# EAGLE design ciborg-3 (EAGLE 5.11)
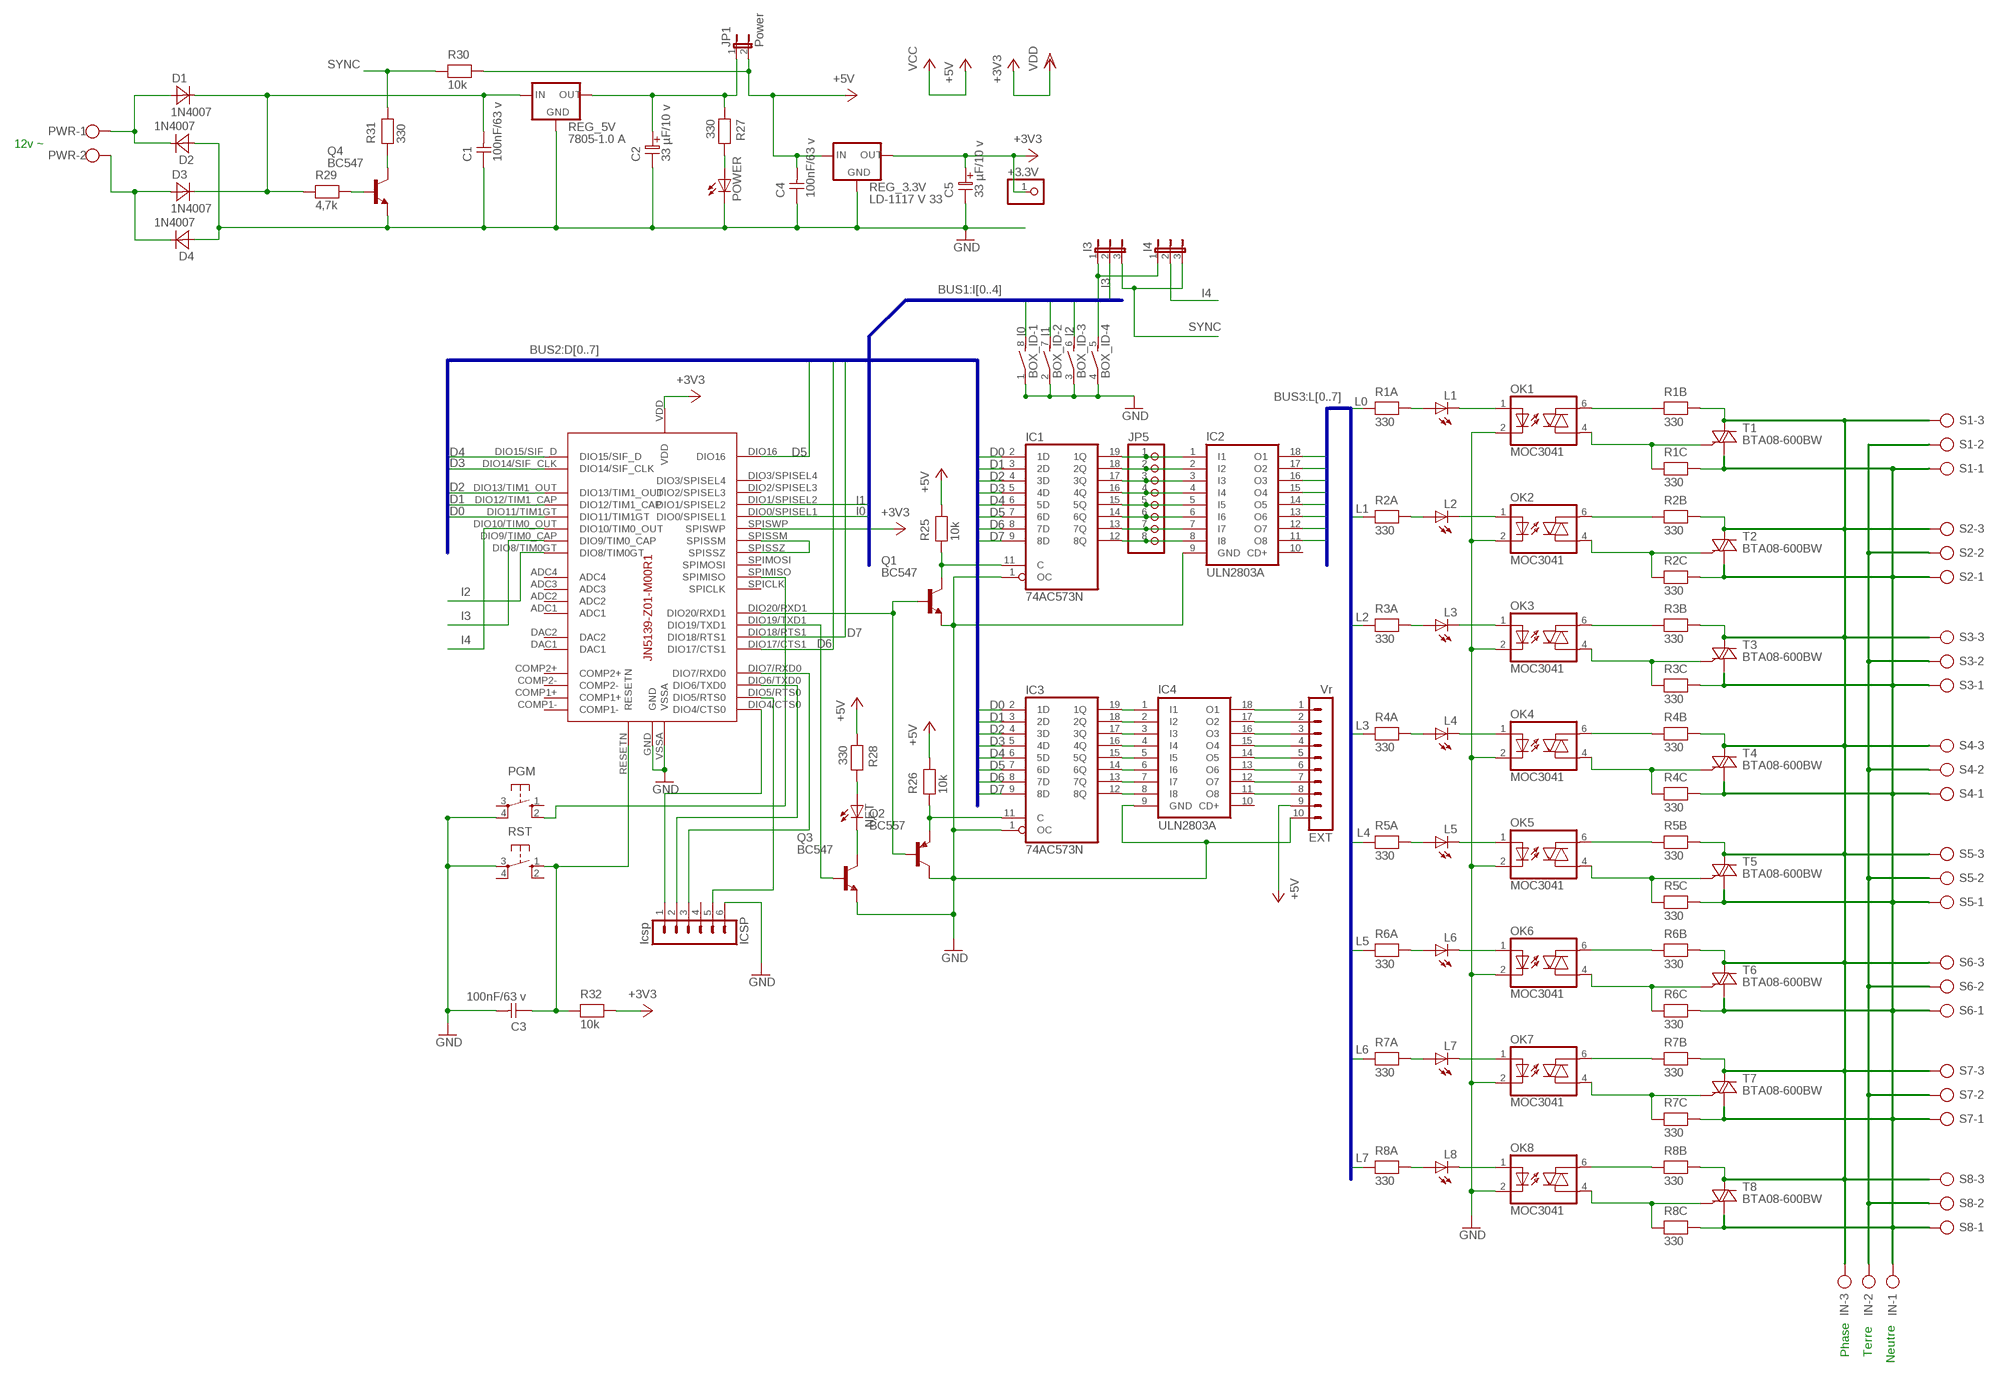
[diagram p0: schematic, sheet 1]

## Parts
+3.3V  PINHD-1X1  [1X01]
BOX_ID  DIP04S  [DIP04S]
C1  100nF/63 v  CAPNP-5  [C-5]
C2  33 µF/10 v  ELC-2,5L  [ES-2,5L]
C3  100nF/63 v  CAPNP-5  [C-5]
C4  100nF/63 v  CAPNP-5  [C-5]
C5  33 µF/10 v  ELC-2,5L  [ES-2,5L]
D1  1N4007  DIODE-10  [D-10]
D2  1N4007  DIODE-10  [D-10]
D3  1N4007  DIODE-10  [D-10]
D4  1N4007  DIODE-10  [D-10]
EXT  Vr  MA10-1  [MA10-1]
I3  JP2E  [JP2]
I4  JP2E  [JP2]
IC1  74AC573N  [DIL20]
IC2  ULN2803A  [DIL18]
IC3  74AC573N  [DIL20]
IC4  ULN2803A  [DIL18]
ICSP  Icsp  MA06-1  [MA06-1]
IN  AK500/3  [AK500/3]
JP1  Power  JP1E  [JP1]
JP5  PINHD-1X8  [1X08]
L1  LED3MM  [LED3MM]
L2  LED3MM  [LED3MM]
L3  LED3MM  [LED3MM]
L4  LED3MM  [LED3MM]
L5  LED3MM  [LED3MM]
L6  LED3MM  [LED3MM]
L7  LED3MM  [LED3MM]
L8  LED3MM  [LED3MM]
NET  LED3MM  [LED3MM]
OK1  MOC3041  IL420  [DIL06]
OK2  MOC3041  IL420  [DIL06]
OK3  MOC3041  IL420  [DIL06]
OK4  MOC3041  IL420  [DIL06]
OK5  MOC3041  IL420  [DIL06]
OK6  MOC3041  IL420  [DIL06]
OK7  MOC3041  IL420  [DIL06]
OK8  MOC3041  IL420  [DIL06]
PGM  10-XX  [B3F-10XX]
POWER  LED3MM  [LED3MM]
PWR  AK550/2  [AK550/2]
Q1  BC547  [TO92]
Q2  BC557  [TO92]
Q3  BC547  [TO92]
Q4  BC547  [TO92]
R1A  330  RESEU-7,5  [R-7,5]
R1B  330  RESEU-7,5  [R-7,5]
R1C  330  RESEU-7,5  [R-7,5]
R2A  330  RESEU-7,5  [R-7,5]
R2B  330  RESEU-7,5  [R-7,5]
R2C  330  RESEU-7,5  [R-7,5]
R3A  330  RESEU-7,5  [R-7,5]
R3B  330  RESEU-7,5  [R-7,5]
R3C  330  RESEU-7,5  [R-7,5]
R4A  330  RESEU-7,5  [R-7,5]
R4B  330  RESEU-7,5  [R-7,5]
R4C  330  RESEU-7,5  [R-7,5]
R5A  330  RESEU-7,5  [R-7,5]
R5B  330  RESEU-7,5  [R-7,5]
R5C  330  RESEU-7,5  [R-7,5]
R6A  330  RESEU-7,5  [R-7,5]
R6B  330  RESEU-7,5  [R-7,5]
R6C  330  RESEU-7,5  [R-7,5]
R7A  330  RESEU-7,5  [R-7,5]
R7B  330  RESEU-7,5  [R-7,5]
R7C  330  RESEU-7,5  [R-7,5]
R8A  330  RESEU-7,5  [R-7,5]
R8B  330  RESEU-7,5  [R-7,5]
R8C  330  RESEU-7,5  [R-7,5]
R25  10k  RESEU-7,5  [R-7,5]
R26  10k  RESEU-7,5  [R-7,5]
R27  330  RESEU-7,5  [R-7,5]
R28  330  RESEU-7,5  [R-7,5]
R29  4,7k  RESEU-7,5  [R-7,5]
R30  10k  RESEU-7,5  [R-7,5]
R31  330  RESEU-7,5  [R-7,5]
R32  10k  RESEU-7,5  [R-7,5]
REG_3.3V  LD-1117 V 33  78XXS  [78XXS]
REG_5V  7805-1.0 A  78XXS  [78XXS]
RST  10-XX  [B3F-10XX]
S1  AK500/3  [AK500/3]
S2  AK500/3  [AK500/3]
S3  AK500/3  [AK500/3]
S4  AK500/3  [AK500/3]
S5  AK500/3  [AK500/3]
S6  AK500/3  [AK500/3]
S7  AK500/3  [AK500/3]
S8  AK500/3  [AK500/3]
T1  BTA08-600BW  TIC225S  [TO220DS]
T2  BTA08-600BW  TIC225S  [TO220DS]
T3  BTA08-600BW  TIC225S  [TO220DS]
T4  BTA08-600BW  TIC225S  [TO220DS]
T5  BTA08-600BW  TIC225S  [TO220DS]
T6  BTA08-600BW  TIC225S  [TO220DS]
T7  BTA08-600BW  TIC225S  [TO220DS]
T8  BTA08-600BW  TIC225S  [TO220DS]
U1  JN5139-Z01-M00R1  [JENNIC5139MODULE]

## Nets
D0: IC1.2(1D) IC3.2(1D) U1.DIO11/TIM1GT
D1: IC1.3(2D) IC3.3(2D) U1.DIO12/TIM1_CAP
D2: IC1.4(3D) IC3.4(3D) U1.DIO13/TIM1_OUT
D3: IC1.5(4D) IC3.5(4D) U1.DIO14/SIF_CLK
D4: IC1.6(5D) IC3.6(5D) U1.DIO15/SIF_D
D5: IC1.7(6D) IC3.7(6D) U1.DIO16
D6: IC1.8(7D) IC3.8(7D) U1.DIO17/CTS1
D7: IC1.9(8D) IC3.9(8D) U1.DIO18/RTS1
GND: BOX_ID.1 BOX_ID.2 BOX_ID.3 BOX_ID.4 C1.1 C2.2 C3.2 C4.1 C5.2 D2.1(A) D4.1(A) EXT.10 IC1.1(OC) IC2.9(GND) IC3.1(OC) IC4.9(GND) ICSP.6 OK1.2(C) OK2.2(C) OK3.2(C) OK4.2(C) OK5.2(C) OK6.2(C) OK7.2(C) OK8.2(C) PGM.4(P1) POWER.K(C) Q1.1(E) Q2.3(C) Q3.1(E) Q4.1(E) REG_3.3V.GND REG_5V.GND RST.3(P) U1.GND U1.VSSA
I0: BOX_ID.8 U1.DIO0/SPISEL1
I1: BOX_ID.7 U1.DIO1/SPISEL2
I2: BOX_ID.6 U1.DIO8/TIM0GT
I3: I3.2 U1.DIO9/TIM0_CAP
I4: I4.2 U1.DIO10/TIM0_OUT
L0: IC2.18(O1) R1A.1
L1: IC2.17(O2) R2A.1
L2: IC2.16(O3) R3A.1
L3: IC2.15(O4) R4A.1
L4: IC2.14(O5) R5A.1
L5: IC2.13(O6) R6A.1
L6: IC2.12(O7) R7A.1
L7: IC2.11(O8) R8A.1
N$1: L4.K(C) OK4.1(A)
N$2: C2.1 JP1.1 R27.1 REG_5V.OUT
N$3: IC1.19(1Q) IC2.1(I1) JP5.1
N$4: IC1.18(2Q) IC2.2(I2) JP5.2
N$5: EXT.1 IC4.18(O1)
N$6: OK2.4(A1) R2C.1 T2.G
N$7: C3.1 R32.1 RST.1(S) U1.RESETN
N$8: OK1.4(A1) R1C.1 T1.G
N$9: EXT.2 IC4.17(O2)
N$10: OK3.4(A1) R3C.1 T3.G
N$11: EXT.3 IC4.16(O3)
N$12: OK4.4(A1) R4C.1 T4.G
N$13: L1.K(C) OK1.1(A)
N$14: EXT.4 IC4.15(O4)
N$15: OK5.4(A1) R5C.1 T5.G
N$16: EXT.5 IC4.14(O5)
N$17: L2.K(C) OK2.1(A)
N$18: OK6.4(A1) R6C.1 T6.G
N$19: L3.K(C) OK3.1(A)
N$20: EXT.6 IC4.13(O6)
N$21: OK7.4(A1) R7C.1 T7.G
N$22: L5.K(C) OK5.1(A)
N$23: EXT.7 IC4.12(O7)
N$24: OK8.4(A1) R8C.1 T8.G
N$25: OK1.6(A2) R1B.1
N$26: OK2.6(A2) R2B.1
N$27: L6.K(C) OK6.1(A)
N$28: EXT.8 IC4.11(O8)
N$29: C1.2 D1.2(K) D3.2(K) R29.1 REG_5V.IN
N$30: OK3.6(A2) R3B.1
N$31: OK4.6(A2) R4B.1
N$32: L7.K(C) OK7.1(A)
N$33: OK5.6(A2) R5B.1
N$34: OK6.6(A2) R6B.1
N$35: OK7.6(A2) R7B.1
N$36: OK8.6(A2) R8B.1
N$37: L8.K(C) OK8.1(A)
N$38: NET.K(C) Q3.3(C)
N$39: IC1.17(3Q) IC2.3(I3) JP5.3
N$40: IC1.16(4Q) IC2.4(I4) JP5.4
N$41: IC1.15(5Q) IC2.5(I5) JP5.5
N$42: IC1.14(6Q) IC2.6(I6) JP5.6
N$43: IC1.13(7Q) IC2.7(I7) JP5.7
N$44: IC1.12(8Q) IC2.8(I8) JP5.8
N$45: IC3.19(1Q) IC4.1(I1)
N$46: IC3.18(2Q) IC4.2(I2)
N$47: IC3.17(3Q) IC4.3(I3)
N$48: IC3.16(4Q) IC4.4(I4)
N$49: IC3.15(5Q) IC4.5(I5)
N$50: IC3.14(6Q) IC4.6(I6)
N$51: IC3.13(7Q) IC4.7(I7)
N$52: IC3.12(8Q) IC4.8(I8)
N$53: L2.A R2A.2
N$54: L3.A R3A.2
N$55: L4.A R4A.2
N$56: L5.A R5A.2
N$57: L6.A R6A.2
N$58: L7.A R7A.2
N$59: L8.A R8A.2
N$60: L1.A R1A.2
N$61: IC1.11(C) Q1.3(C) R25.1
N$62: NET.A R28.2
N$63: IC3.11(C) Q2.1(E) R26.1
N$64: Q1.2(B) Q2.2(B) U1.DIO20/RXD1
N$65: POWER.A R27.2
N$66: BOX_ID.5 I3.1 I4.1
N$67: ICSP.2 U1.DIO6/TXD0
N$68: D1.1(A) D2.2(K) PWR.1
N$69: D3.1(A) D4.2(K) PWR.2
N$70: PGM.2(S1) U1.SPIMISO
N$71: Q4.2(B) R29.2
N$72: Q4.3(C) R31.1
N$73: ICSP.1 U1.DIO4/CTS0
N$74: ICSP.5 U1.DIO5/RTS0
N$75: Q3.2(B) U1.DIO19/TXD1
N$76: U1.SPISSM U1.SPISSZ
N$77: ICSP.3 U1.DIO7/RXD0
NEUTRE [AC_VOLTAGE]: IN.1 R1C.2 R2C.2 R3C.2 R4C.2 R5C.2 R6C.2 R7C.2 R8C.2 S1.1 S2.1 S3.1 S4.1 S5.1 S6.1 S7.1 S8.1 T1.A1 T2.A1 T3.A1 T4.A1 T5.A1 T6.A1 T7.A1 T8.A1
PHASE [AC_VOLTAGE]: IN.3 R1B.2 R2B.2 R3B.2 R4B.2 R5B.2 R6B.2 R7B.2 R8B.2 S1.3 S2.3 S3.3 S4.3 S5.3 S6.3 S7.3 S8.3 T1.A2 T2.A2 T3.A2 T4.A2 T5.A2 T6.A2 T7.A2 T8.A2
SYNC: I3.3 I4.3 R30.1 R31.2
TERRE: IN.2 S1.2 S2.2 S3.2 S4.2 S5.2 S6.2 S7.2 S8.2
VCC: C4.2 EXT.9 JP1.2 R25.2 R26.2 R28.1 R30.2 REG_3.3V.IN ; supply symbol labelled +5V
VDD: +3.3V.1 C5.1 R32.2 REG_3.3V.OUT U1.SPISWP U1.VDD ; supply symbol labelled +3V3
Unconnected: IC2.10(CD+) IC4.10(CD+) ICSP.4 PGM.1(S) PGM.3(P) RST.2(S1) RST.4(P1) U1.ADC1 U1.ADC2 U1.ADC3 U1.ADC4 U1.COMP1+ U1.COMP1- U1.COMP2+ U1.COMP2- U1.DAC1 U1.DAC2 U1.DIO2/SPISEL3 U1.DIO3/SPISEL4 U1.SPICLK U1.SPIMOSI

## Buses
BUS3:L[0..7]
BUS2:D[0..7]
BUS1:I[0..4]

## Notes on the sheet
- 12v ~
- Phase | Neutre
- Terre

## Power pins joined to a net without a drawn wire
GND: IC1.10(GND) IC3.10(GND)
VCC: IC1.20(VCC) IC3.20(VCC)

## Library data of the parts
+3.3V = pinhead:PINHD-1X1: PIN HEADER
BOX_ID = switch-dil:DIP04S: DIL/CODE SWITCH; OC_FARNELL: unknown; OC_NEWARK: unknown
C1 C3 C4 = discrete:CAPNP-5
C2 C5 = discrete:ELC-2,5L
D1-D4 = discrete:DIODE-10
EXT = con-lstb:MA10-1: PIN HEADER; OC_FARNELL: unknown; OC_NEWARK: unknown
I3 I4 = jumper:JP2E: JUMPER
IC1 IC3 = 74xx-eu:74*573: 8-bit D latch BUS DRIVER
IC2 IC4 = uln-udn:ULN2803A: DRIVER ARRAY
ICSP = con-lstb:MA06-1: PIN HEADER; OC_FARNELL: unknown; OC_NEWARK: unknown
IN S1-S8 = con-ptr500:AK500/3: CONNECTOR
JP1 = jumper:JP1E: JUMPER
JP5 = pinhead:PINHD-1X8: PIN HEADER
L1-L8 NET POWER = led:LED: LED
OK1-OK8 = optocoupler:IL420: SIEMENS OPTO COUPLER
PGM RST = switch-omron:10-XX: OMRON SWITCH; MPN: B3F-1000; OC_FARNELL: 176432; OC_NEWARK: 36M3542
PWR = con-ptr500+:AK550/2: CONNECTOR
Q1 Q3 Q4 = transistor:BC547: NPN TRANSISTOR
Q2 = transistor-pnp:BC557: PNP Transistor
R1A R1B R1C R2A R2B R2C R3A R3B R3C R4A R4B R4C R5A R5B R5C R6A R6B R6C R7A R7B R7C R8A R8B R8C R25-R32 = discrete:RESEU-7,5
REG_3.3V REG_5V = v-reg:78XXS: VOLTAGE REGULATOR
T1-T8 = triac:TIC225S: TRIAC
U1 = jennic:JN5139-Z01-M00R1: Jennic 5139 Zigbee Module

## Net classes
0 default: width 0.254 mm, clearance 0.254 mm
1 AC_VOLTAGE: width 1.5 mm, clearance 0.254 mm
2 AC_TERRE: width 1.422 mm, clearance 0.254 mm

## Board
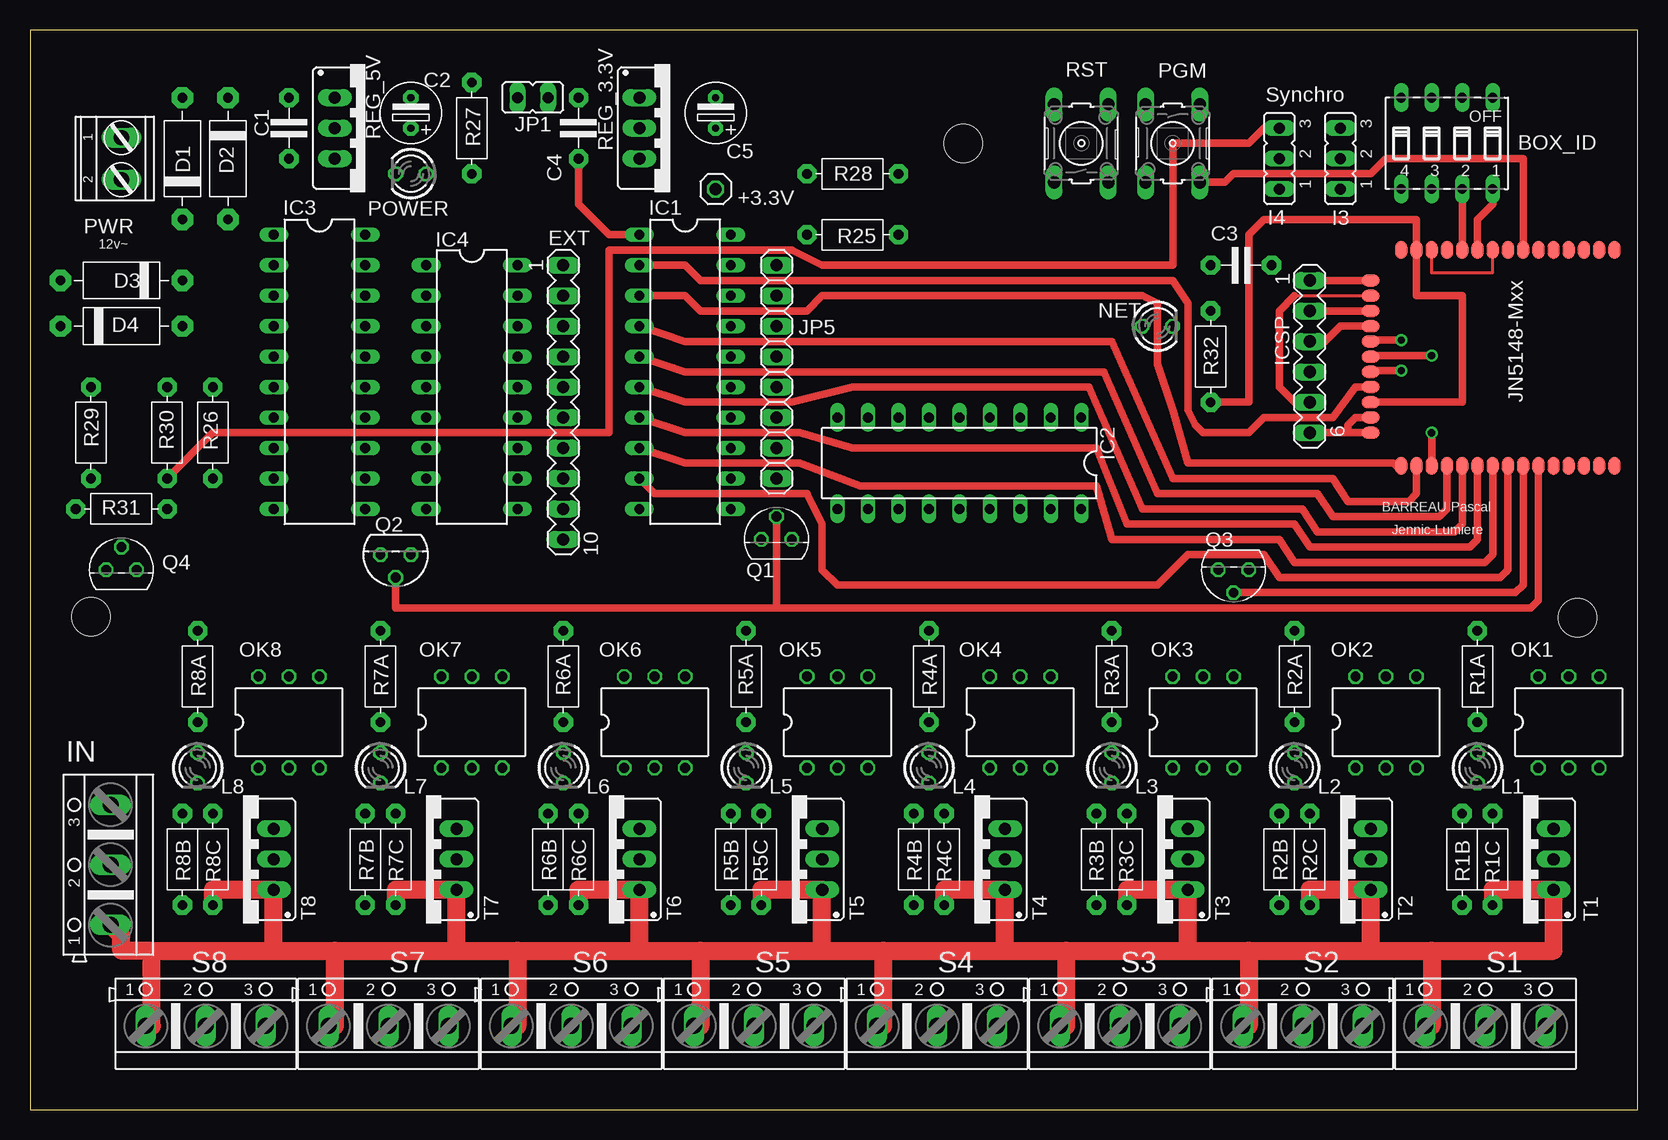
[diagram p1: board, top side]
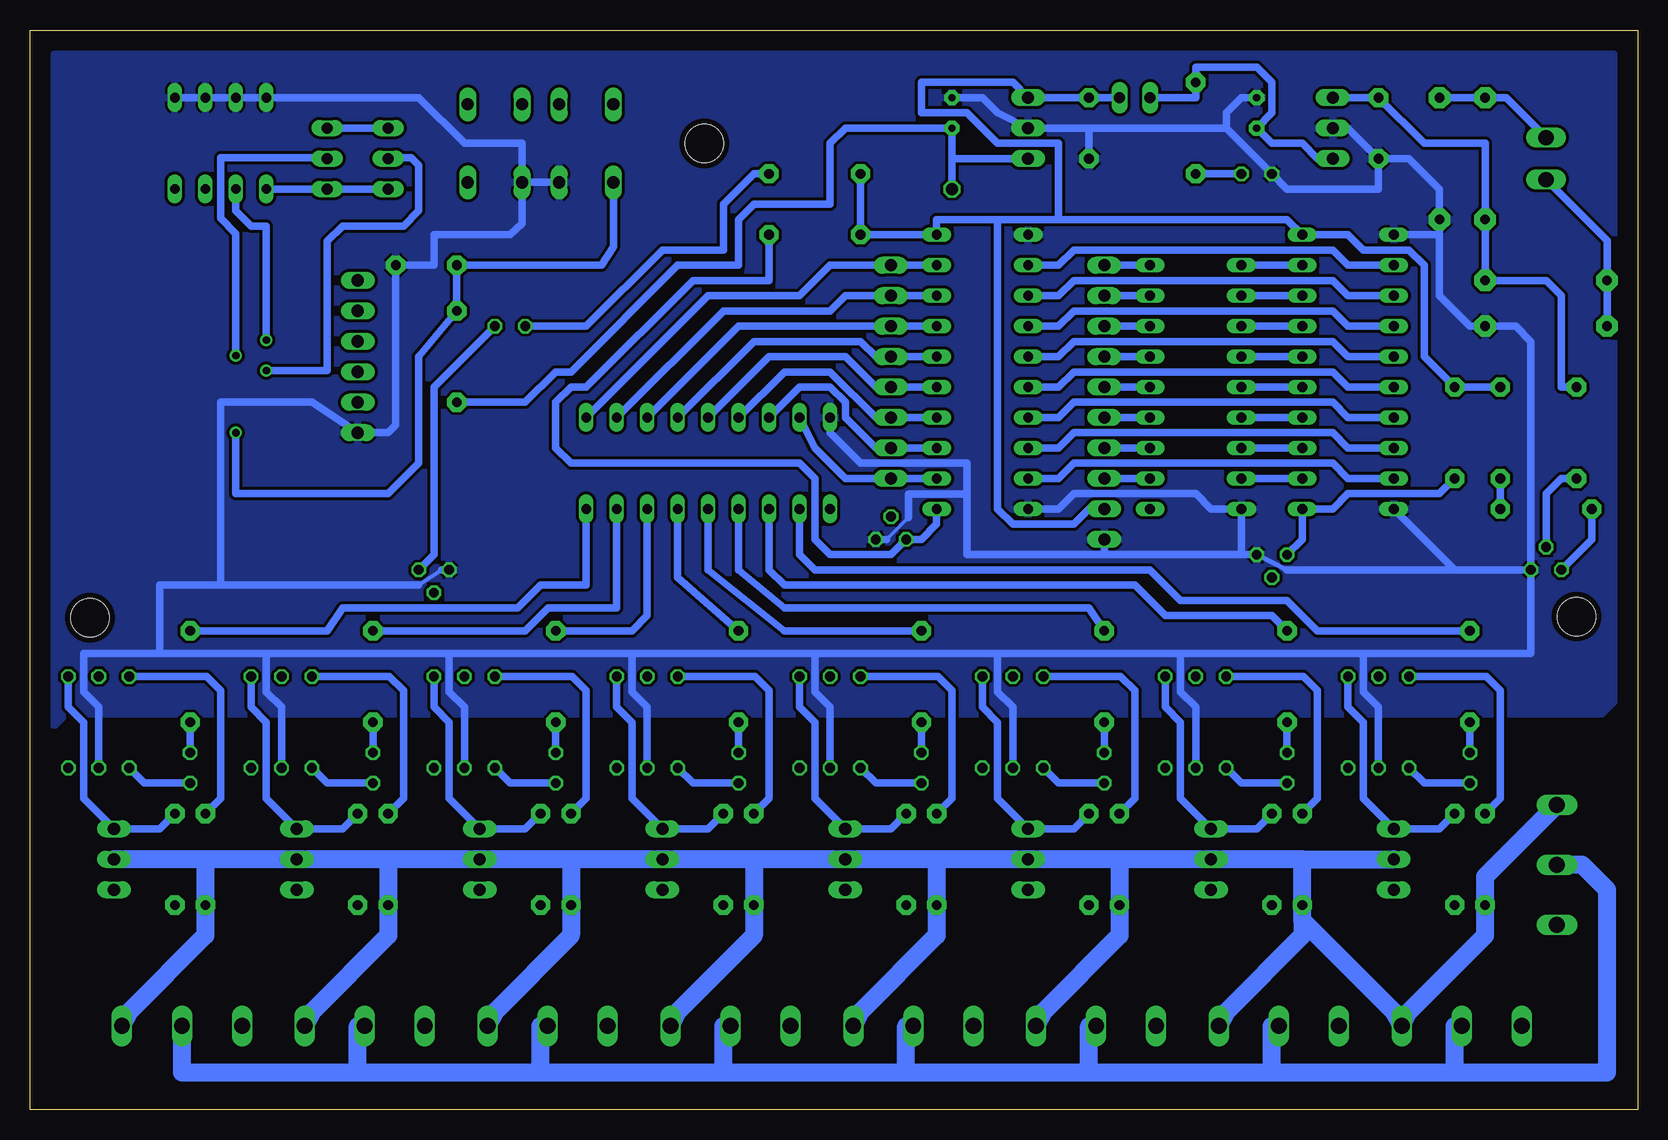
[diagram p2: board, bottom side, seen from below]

Size 134 x 90 mm. Coordinates in mm from the lower left corner, seen from the top.
Outline: 0,0 134,0 134,90 0,90 0,0
Copper layers (1*16): Top 0.018mm / dielectric 1.55mm / Bottom 0.018mm
Design rules "eC-PCB_proto-2-layer": minimum track width 0.15mm, minimum drill 0.25mm, track to track 0.15mm, track to pad 0.15mm, pad to pad 0.15mm, via to via 0.15mm, smd to smd 0.15mm, copper to edge 0.45mm, drill to drill 0.3mm, minimum pad ring 0.2mm, minimum via ring 0.2mm, stop-mask expansion 0.1mm, vias tented up to drill 0mil, thermal gap 0.2mm
Holes 3.2 mm at 129,41 77.8,80.55 5.08,41.1

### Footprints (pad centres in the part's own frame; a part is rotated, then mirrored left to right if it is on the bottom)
1X01 = drill 1.016 octagon: 1 0,0
DIP04S = drill 0.813 long: 1 -3.81,-3.81; 2 -1.27,-3.81; 3 1.27,-3.81; 4 3.81,-3.81; 5 3.81,3.81; 6 1.27,3.81; 7 -1.27,3.81; 8 -3.81,3.81
C-5 = drill 0.813 pad 1.6 octagon: 1 -2.54,0; 2 2.54,0
ES-2,5L = drill 0.61 pad 1.27 octagon: 1 0,0; 2 2.54,0
D-10 = drill 0.813 pad 1.778 octagon: 1 -5.08,0; 2 5.08,0
MA10-1 = drill 1.016 long: 1 -11.43,0; 2 -8.89,0; 3 -6.35,0; 4 -3.81,0; 5 -1.27,0; 6 1.27,0; 7 3.81,0; 8 6.35,0; 9 8.89,0; 10 11.43,0
JP2 = drill 0.914 long: 1 -2.54,0; 2 0,0; 3 2.54,0
DIL20 = drill 0.813 long: 1 -11.43,-3.81; 2 -8.89,-3.81; 3 -6.35,-3.81; 4 -3.81,-3.81; 5 -1.27,-3.81; 6 1.27,-3.81; 7 3.81,-3.81; 8 6.35,-3.81; 9 8.89,-3.81; 10 11.43,-3.81; 11 11.43,3.81; 12 8.89,3.81; 13 6.35,3.81; 14 3.81,3.81; 15 1.27,3.81; 16 -1.27,3.81; 17 -3.81,3.81; 18 -6.35,3.81; 19 -8.89,3.81; 20 -11.43,3.81
DIL18 = drill 0.813 long: 1 -10.16,-3.81; 2 -7.62,-3.81; 3 -5.08,-3.81; 4 -2.54,-3.81; 5 0,-3.81; 6 2.54,-3.81; 7 5.08,-3.81; 8 7.62,-3.81; 9 10.16,-3.81; 10 10.16,3.81; 11 7.62,3.81; 12 5.08,3.81; 13 2.54,3.81; 14 0,3.81; 15 -2.54,3.81; 16 -5.08,3.81; 17 -7.62,3.81; 18 -10.16,3.81
MA06-1 = drill 1.016 long: 1 -6.35,0; 2 -3.81,0; 3 -1.27,0; 4 1.27,0; 5 3.81,0; 6 6.35,0
AK500/3 = drill 1.321 long: 1 -5.004,0; 2 0,0; 3 5.004,0
JP1 = drill 0.914 long: 1 0,-1.27; 2 0,1.27
1X08 = drill 1.016 long: 1 -8.89,0; 2 -6.35,0; 3 -3.81,0; 4 -1.27,0; 5 1.27,0; 6 3.81,0; 7 6.35,0; 8 8.89,0
LED3MM = drill 0.813 octagon: A -1.27,0; K 1.27,0
DIL06 = drill 0.813 octagon: 1 -2.54,-3.81; 2 0,-3.81; 3 2.54,-3.81; 4 2.54,3.81; 5 0,3.81; 6 -2.54,3.81
B3F-10XX = drill 1.016 long: 1 -3.251,2.261; 2 3.251,2.261; 3 -3.251,-2.261; 4 3.251,-2.261
AK550/2 = drill 1.27 long: 1 -1.75,0; 2 1.75,0
TO92 = drill 0.813 octagon: 1 1.27,0; 2 0,1.905; 3 -1.27,0
R-7,5 = drill 0.813 pad 1.6 octagon: 1 -3.81,0; 2 3.81,0
78XXS = drill 1.016 long: GND 0,-2.54; IN -2.54,-2.54; OUT 2.54,-2.54
TO220DS = drill 1.016 long: A1 -2.54,-2.54; A2 0,-2.54; G 2.54,-2.54
JENNIC5139MODULE = smd 1.5 x 1: ADC1 18,17.78; ADC2 18,19.05; ADC3 18,20.32; ADC4 0,20.32; COMP1+ 18,16.51; COMP1- 18,15.24; COMP2+ 0,16.51; COMP2- 0,15.24; DAC1 0,19.05; DAC2 0,17.78; DIO0/SPISEL1 0,8.89; DIO1/SPISEL2 0,7.62; DIO2/SPISEL3 0,6.35; DIO3/SPISEL4 0,2.54; DIO12/TIM1_CAP 18,2.54; DIO13/TIM1_OUT 18,3.81; DIO14/SIF_CLK 18,6.35; DIO15/SIF_D 18,7.62; DIO16 18,8.89; DIO17/CTS1 18,10.16; DIO18/RTS1 18,11.43; DIO19/TXD1 18,12.7; DIO20/RXD1 18,13.97; RESETN 18,5.08; SPICLK 0,13.97; SPIMISO 0,12.7; SPIMOSI 0,11.43; SPISSM 0,5.08; SPISSZ 0,10.16; SPISWP 0,3.81 | smd 1 x 1.5: DIO4/CTS0 2.54,0; DIO5/RTS0 3.81,0; DIO6/TXD0 5.08,0; DIO7/RXD0 6.35,0; DIO8/TIM0GT 7.62,0; DIO9/TIM0_CAP 8.89,0; DIO10/TIM0_OUT 10.16,0; DIO11/TIM1GT 11.43,0; GND 13.97,0; VDD 12.7,0; VSSA 15.24,0

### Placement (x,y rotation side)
+3.3V  57.15,76.74 0 top
BOX_ID  118.11,80.55 180 top
C1  21.59,81.82 90 top
C2  31.75,81.82 90 top
C3  100.97,70.39 0 top
C4  45.72,81.82 90 top
C5  57.15,81.82 90 top
D1  12.7,79.28 270 top
D2  16.51,79.28 90 top
D3  7.62,69.12 0 top
D4  7.62,65.31 180 top
EXT  44.45,58.96 270 top
I3  109.22,79.28 90 top
I4  104.14,79.28 90 top
IC1  54.61,61.5 270 top
IC2  77.47,53.88 180 top
IC3  24.13,61.5 270 top
IC4  36.83,60.23 270 top
ICSP  106.68,62.77 270 top
IN  6.72,20.4 90 top
JP1  41.91,84.36 270 top
JP5  62.23,61.5 270 top
L1  120.65,28.48 270 top
L2  105.41,28.48 270 top
L3  90.17,28.48 270 top
L4  74.93,28.48 270 top
L5  59.69,28.48 270 top
L6  44.45,28.48 270 top
L7  29.21,28.48 270 top
L8  13.97,28.48 270 top
NET  93.98,65.31 0 top
OK1  128.27,32.29 0 top
OK2  113.03,32.29 0 top
OK3  97.79,32.29 0 top
OK4  82.55,32.29 0 top
OK5  67.31,32.29 0 top
OK6  52.07,32.29 0 top
OK7  36.83,32.29 0 top
OK8  21.59,32.29 0 top
PGM  95.25,80.55 270 top
POWER  31.75,78.01 180 top
PWR  7.62,79.28 270 top
Q1  62.23,47.53 0 top
Q2  30.48,46.26 180 top
Q3  100.33,44.99 180 top
Q4  7.62,44.99 0 top
R1A  120.65,36.1 270 top
R1B  119.38,20.86 270 top
R1C  121.92,20.86 270 top
R2A  105.41,36.1 270 top
R2B  104.14,20.86 270 top
R2C  106.68,20.86 270 top
R3A  90.17,36.1 270 top
R3B  88.9,20.86 270 top
R3C  91.44,20.86 270 top
R4A  74.93,36.1 270 top
R4B  73.66,20.86 270 top
R4C  76.2,20.86 270 top
R5A  59.69,36.1 270 top
R5B  58.42,20.86 270 top
R5C  60.96,20.86 270 top
R6A  44.45,36.1 270 top
R6B  43.18,20.86 270 top
R6C  45.72,20.86 270 top
R7A  29.21,36.1 270 top
R7B  27.94,20.86 270 top
R7C  30.48,20.86 270 top
R8A  13.97,36.1 270 top
R8B  12.7,20.86 270 top
R8C  15.24,20.86 270 top
R25  68.58,72.93 180 top
R26  15.24,56.42 90 top
R27  36.83,81.82 270 top
R28  68.58,78.01 0 top
R29  5.08,56.42 270 top
R30  11.43,56.42 90 top
R31  7.62,50.07 0 top
R32  98.42,62.77 270 top
REG_3.3V  53.34,81.82 270 top
REG_5V  27.94,81.82 270 top
RST  87.63,80.55 90 top
S1  121.33,6.97 0 top
S2  106.09,6.97 0 top
S3  90.85,6.97 0 top
S4  75.61,6.97 0 top
S5  60.37,6.97 0 top
S6  45.13,6.97 0 top
S7  29.89,6.97 0 top
S8  14.65,6.97 0 top
T1  124.46,20.86 90 top
T2  109.22,20.86 90 top
T3  93.98,20.86 90 top
T4  78.74,20.86 90 top
T5  63.5,20.86 90 top
T6  48.26,20.86 90 top
T7  33.02,20.86 90 top
T8  17.78,20.86 90 top
U1  111.76,71.66 270 top

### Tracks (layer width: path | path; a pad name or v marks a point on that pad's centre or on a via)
D0
  Top 0.61: IC1.2 54.61,70.39 55.88,69.12 95.25,69.12 96.52,67.22 96.52,58.33 97.16,57.05 97.79,56.42 101.6,56.42 102.87,57.69 108.58,57.69 110.49,60.23 U1.DIO11/TIM1GT
  Bottom 0.61: IC3.2 24.13,70.39 25.4,71.66 46.99,71.66 48.26,70.39 IC1.2
D1
  Top 0.61: IC1.3 54.61,67.85 55.88,66.58 64.77,66.58 66.04,67.85 92.71,67.85 93.98,67.22 93.98,62.13 95.25,58.33 96.52,53.88 113.67,53.88 113.89,53.66 U1.DIO12/TIM1_CAP
  Bottom 0.61: IC3.3 24.13,67.85 25.4,69.12 46.99,69.12 48.26,67.85 IC1.3
D2
  Top 0.254: U1.DIO13/TIM1_OUT 115.57,53.88
  Top 0.61: IC1.4 54.61,64.04 90.17,64.04 95.25,52.61 108.58,52.61 109.86,50.7 114.94,50.7 115.57,51.34 U1.DIO13/TIM1_OUT
  Bottom 0.61: IC3.4 24.13,65.31 25.4,66.58 46.99,66.58 48.26,65.31 IC1.4
D3
  Top 0.61: IC1.5 54.61,61.5 89.53,61.5 93.98,51.34 107.31,51.34 108.58,49.44 117.47,49.44 118.11,50.07 U1.DIO14/SIF_CLK
  Bottom 0.61: IC3.5 24.13,62.77 25.4,64.04 46.99,64.04 48.26,62.77 IC1.5
D4
  Top 0.61: IC1.6 54.61,58.96 63.5,58.96 68.58,60.23 88.27,60.23 92.71,50.07 106.05,50.07 107.31,48.16 118.75,48.16 119.38,48.8 U1.DIO15/SIF_D
  Bottom 0.61: IC3.6 24.13,60.23 25.4,61.5 46.99,61.5 48.26,60.23 IC1.6
D5
  Top 0.61: IC1.7 54.61,56.42 64.14,56.42 68.58,55.15 88.9,55.15 91.44,48.8 105.41,48.8 106.68,46.9 120.02,46.9 120.65,47.53 U1.DIO16
  Bottom 0.61: IC3.7 24.13,57.69 25.4,58.96 46.99,58.96 48.26,57.69 IC1.7
D6
  Top 0.61: IC1.8 54.61,53.88 64.14,53.88 69.22,51.98 88.9,51.98 90.17,47.53 104.14,47.53 105.41,45.62 121.28,45.62 121.92,46.26 U1.DIO17/CTS1
  Bottom 0.61: IC3.8 24.13,55.15 25.4,56.42 46.99,56.42 48.26,55.15 IC1.8
D7
  Top 0.254: U1.DIO18/RTS1 123.19,53.88
  Top 0.61: U1.DIO18/RTS1 123.19,44.99 122.56,44.35 104.14,44.35 102.87,46.26 96.52,46.26 93.98,43.72 67.31,43.72 66.04,44.99 66.04,48.8 64.77,51.34 52.07,51.34 IC1.9
  Bottom 0.61: IC3.9 24.13,52.61 25.4,53.88 46.99,53.88 48.26,52.61 IC1.9
GND
  Top 0.61: ICSP.6 109.86,56.42 | 109.86,56.42 U1.VSSA | C4.1 45.72,75.47 48.26,72.93 IC1.1 | U1.GND 110.49,57.69 109.86,57.05 109.86,56.42
  Bottom 0.305: 60.76,49.37 62.6,47.53 | 55.91,51.31 55.88,51.34 | 101.6,43.72 99.69,44.99
  Bottom 0.406: 29.21,44.99 Q2.3
  Bottom 0.61: REG_3.3V.GND 49.53,81.82 | REG_3.3V.GND 53.34,83.09 54.61,84.36 C5.2 | C1.1 24.13,81.82 REG_5V.GND | C1.1 19.05,79.28 16.51,76.74 D2.1 16.51,72.93 | C2.2 33.02,84.36 34.29,83.09 34.29,81.82 | 34.29,81.82 POWER.K 29.21,76.74 21.59,76.74 C1.1 | 34.29,81.82 45.72,81.82 | 45.72,81.82 REG_3.3V.GND | 45.72,81.82 C4.1 | BOX_ID.1 BOX_ID.2 BOX_ID.3 BOX_ID.4 101.6,84.36 97.79,80.55 92.98,80.55 92.98,78.29 PGM.4 | IC1.10 48.26,50.07 46.99,51.34 36.83,51.34 35.56,50.07 IC4.9 33.02,46.26 | 33.02,46.26 44.45,46.26 | 44.45,46.26 EXT.10 | 16.51,72.93 16.51,67.85 13.97,65.31 D4.1 10.16,65.31 8.89,64.04 Q4.1 | 16.51,72.93 IC3.1 | 15.24,44.99 IC3.10 | Q4.1 15.24,44.99 | 15.24,44.99 29.21,44.99 | Q2.3 33.02,46.26 | 55.88,51.34 55.88,53.88 64.77,53.88 67.31,56.42 IC2.9 | 62.6,47.53 Q1.1 | 60.76,49.37 60.76,51.31 55.91,51.31 55.88,51.29 55.88,46.26 44.45,46.26 | PGM.4 RST.3 | PGM.4 92.99,73.84 93.98,72.93 100.33,72.93 100.33,70.39 C3.2 103.5,57.05 104.14,56.42 ICSP.6 110.49,58.96 118.11,58.96 118.11,43.72 | 99.69,44.99 Q3.1 | 118.11,43.72 101.6,43.72 | OK8.2 21.59,33.56 22.86,34.83 22.86,38.01 | 114.3,38.01 114.3,34.83 113.03,33.56 OK2.2 | 118.11,43.72 123.19,43.72 123.19,38.01 | 114.3,38.01 123.19,38.01 | 22.86,38.01 38.1,38.01 | 38.1,38.01 53.34,38.01 | 53.34,38.01 68.58,38.01 | 68.58,38.01 83.82,38.01 | 83.82,38.01 99.06,38.01 | 99.06,38.01 114.3,38.01 | OK7.2 36.83,33.56 38.1,34.83 38.1,38.01 | OK6.2 52.07,33.56 53.34,34.83 53.34,38.01 | OK5.2 67.31,33.56 68.58,34.83 68.58,38.01 | OK4.2 82.55,33.56 83.82,34.83 83.82,38.01 | OK3.2 97.79,33.56 99.06,34.83 99.06,38.01 | OK1.2 128.27,33.56 129.54,34.83 129.54,38.01 123.19,38.01
  Bottom 0.61: 22.86,38.01 8.89,38.01 Q4.1
  pour Bottom: 2,88 132,88 132,32 131,33 3,33 2,34
I0
  Top 0.61: U1.DIO0/SPISEL1 120.65,74.2 121.92,75.47 BOX_ID.8
I1
  Top 0.61: U1.DIO1/SPISEL2 BOX_ID.7
I2  (via drill 0.6)
  Top 0.61: U1.DIO8/TIM0GT 111.86,64.14 v114.3,64.14
  Bottom 0.61: BOX_ID.6 116.84,74.93 115.57,73.66 114.3,73.66 v114.3,64.14
I3  (via drill 0.6)
  Top 0.61: U1.DIO9/TIM0_CAP 111.86,62.87 v116.84,62.87
  Bottom 0.61: I3.2 109.31,79.38 118.11,79.38 118.11,74.3 116.84,73.03 v116.84,62.87
I4  (via drill 0.6)
  Top 0.61: U1.DIO10/TIM0_OUT 111.86,61.59 v114.3,61.59
  Bottom 0.61: I4.2 104.05,79.38 102.23,79.38 101.6,78.74 101.6,74.93 102.87,73.66 107.95,73.66 109.22,72.39 109.22,61.59 v114.3,61.59
L0
  Bottom 0.61: IC2.18 87.63,43.72 91.44,43.72 93.34,41.81 107.95,41.81 109.22,39.91 R1A.1
L1
  Bottom 0.61: IC2.17 85.09,41.81 90.81,41.81 92.71,39.91 R2A.1
L2
  Bottom 0.61: IC2.16 82.55,41.18 83.82,39.91 R3A.1
L3
  Bottom 0.61: IC2.15 80.01,44.35 R4A.1
L4
  Bottom 0.61: IC2.14 77.47,44.99 71.12,39.91 R5A.1
L5
  Bottom 0.61: IC2.13 74.93,44.99 71.12,41.81 45.72,41.81 R6A.1
L6
  Bottom 0.61: R7A.1 30.48,41.18 39.37,41.18 41.91,43.72 71.12,43.72 72.39,44.99 IC2.12
L7
  Bottom 0.61: R8A.1 26.67,39.91 29.21,42.45 38.1,42.45 40.64,44.99 68.58,44.99 69.85,46.26 IC2.11
N$1
  Bottom 0.61: L4.K 78.74,27.21 OK4.1
N$2
  Bottom 0.61: REG_5V.OUT 26.67,79.28 27.94,80.55 30.48,80.55 C2.1 30.48,83.09 30.48,85.63 31.75,86.9 36.83,86.9 R27.1 36.83,84.36 JP1.1
N$3
  Bottom 0.61: IC2.1 77.47,67.85 69.85,67.85 67.31,70.39 JP5.1 IC1.19
N$4
  Bottom 0.61: IC2.2 76.2,66.58 67.31,66.58 66.04,67.85 JP5.2 IC1.18
N$5
  Bottom 0.61: IC4.18 EXT.1
N$6
  Bottom 0.61: R2C.1 107.95,23.4 T2.G 114.3,25.94 114.3,32.29 115.57,33.56 OK2.4
N$7  (via drill 0.6)
  Top 0.61: v116.84,56.42 U1.RESETN
  Bottom 0.61: RST.1 85.37,71.94 86.36,70.39 C3.1 R32.1 101.6,62.77 101.6,53.88 104.14,51.34 116.84,51.34 v116.84,56.42
N$8
  Bottom 0.61: R1C.1 123.19,23.4 T1.G 129.54,25.94 129.54,32.29 130.81,33.56 OK1.4
N$9
  Bottom 0.61: IC4.17 EXT.2
N$10
  Bottom 0.61: R3C.1 92.71,23.4 T3.G 99.06,25.94 99.06,32.29 100.33,33.56 OK3.4
N$11
  Bottom 0.61: IC4.16 EXT.3
N$12
  Bottom 0.61: R4C.1 77.47,23.4 T4.G 83.82,25.94 83.82,32.29 85.09,33.56 OK4.4
N$13
  Bottom 0.61: L1.K 124.46,27.21 OK1.1
N$14
  Bottom 0.61: IC4.15 EXT.4
N$15
  Bottom 0.61: R5C.1 62.23,23.4 T5.G 68.58,25.94 68.58,32.29 69.85,33.56 OK5.4
N$16
  Bottom 0.61: IC4.14 EXT.5
N$17
  Bottom 0.61: L2.K 109.22,27.21 OK2.1
N$18
  Bottom 0.61: R6C.1 46.99,23.4 T6.G 53.34,25.94 53.34,32.29 54.61,33.56 OK6.4
N$19
  Bottom 0.61: L3.K 93.98,27.21 OK3.1
N$20
  Bottom 0.61: IC4.13 EXT.6
N$21
  Bottom 0.61: R7C.1 31.75,23.4 T7.G 38.1,25.94 38.1,32.29 39.37,33.56 OK7.4
N$22
  Bottom 0.61: L5.K 63.5,27.21 OK5.1
N$23
  Bottom 0.61: IC4.12 EXT.7
N$24
  Bottom 0.61: R8C.1 16.51,23.4 T8.G 22.86,25.94 22.86,32.29 24.13,33.56 OK8.4
N$25
  Bottom 0.61: R1B.1 118.11,25.94 118.11,34.92 119.28,36.1 OK1.6
N$26
  Bottom 0.61: R2B.1 102.87,25.94 102.87,34.92 104.05,36.1 OK2.6
N$27
  Bottom 0.61: L6.K 48.26,27.21 OK6.1
N$28
  Bottom 0.61: IC4.11 EXT.8
N$29
  Bottom 0.61: REG_5V.IN C1.2 17.78,80.55 12.7,80.55 D1.2 D3.2 7.62,69.12 6.35,67.85 6.35,60.23 R29.1
N$30
  Bottom 0.61: R3B.1 87.63,25.94 87.63,34.92 88.81,36.1 OK3.6
N$31
  Bottom 0.61: R4B.1 72.39,25.94 72.39,34.92 73.56,36.1 OK4.6
N$32
  Bottom 0.61: L7.K 33.02,27.21 OK7.1
N$33
  Bottom 0.61: R5B.1 57.15,25.94 57.15,34.92 58.33,36.1 OK5.6
N$34
  Bottom 0.61: R6B.1 41.91,25.94 41.91,34.92 43.09,36.1 OK6.6
N$35
  Bottom 0.61: R7B.1 26.67,25.94 26.67,34.92 27.84,36.1 OK7.6
N$36
  Bottom 0.61: R8B.1 11.43,25.94 11.43,34.92 12.61,36.1 OK8.6
N$37
  Bottom 0.61: L8.K 17.78,27.21 OK8.1
N$38
  Bottom 0.61: NET.K 100.33,60.23 100.33,46.26 Q3.3
N$39
  Bottom 0.61: IC2.3 74.93,65.31 IC1.17 JP5.3
N$40
  Bottom 0.61: IC2.4 73.66,64.04 64.77,64.04 63.5,62.77 JP5.4 IC1.16
N$41
  Bottom 0.61: IC2.5 72.39,62.77 66.04,62.77 63.5,60.23 JP5.5 IC1.15
N$42
  Bottom 0.61: IC2.6 71.12,61.5 67.31,61.5 63.5,57.69 JP5.6 IC1.14
N$43
  Bottom 0.61: IC2.7 69.85,60.23 67.31,60.23 66.04,58.96 66.04,57.69 63.5,55.15 JP5.7 IC1.13
N$44
  Bottom 0.61: IC2.8 68.58,55.15 66.04,52.61 JP5.8 IC1.12
N$45
  Bottom 0.61: IC3.19 IC4.1
N$46
  Bottom 0.61: IC3.18 IC4.2
N$47
  Bottom 0.61: IC3.17 IC4.3
N$48
  Bottom 0.61: IC3.16 IC4.4
N$49
  Bottom 0.61: IC3.15 IC4.5
N$50
  Bottom 0.61: IC3.14 IC4.6
N$51
  Bottom 0.61: IC3.13 IC4.7
N$52
  Bottom 0.61: IC3.12 IC4.8
N$53
  Bottom 0.61: L2.A R2A.2
N$54
  Bottom 0.61: L3.A R3A.2
N$55
  Bottom 0.61: L4.A R4A.2
N$56
  Bottom 0.61: L5.A R5A.2
N$57
  Bottom 0.61: L6.A R6A.2
N$58
  Bottom 0.61: L7.A R7A.2
N$59
  Bottom 0.61: L8.A R8A.2
N$60
  Bottom 0.61: L1.A R1A.2
N$61
  Bottom 0.61: IC1.11 58.42,48.8 59.69,47.53 Q1.3 62.23,46.26 67.31,46.26 68.58,47.53 68.58,52.61 69.85,53.88 88.9,53.88 90.17,55.15 90.17,58.96 88.9,60.23 87.63,60.23 78.74,69.12 72.39,69.12 R25.1
N$62
  Bottom 0.61: R28.2 73.66,78.01 76.2,75.47 76.2,71.66 81.28,71.66 87.63,65.31 NET.A
N$63
  Bottom 0.61: Q2.1 27.94,47.53 IC3.11 25.4,50.07 24.13,51.34 16.51,51.34 R26.1
N$64
  Top 0.61: 125.73,53.88 U1.DIO20/RXD1 125.73,42.45 125.09,41.81 62.23,41.81 | 62.23,41.81 Q1.2 | Q2.2 30.48,41.81 62.23,41.81
N$65
  Bottom 0.61: POWER.A R27.2
N$66
  Bottom 0.61: I4.1 I3.1 BOX_ID.5
N$67
  Top 0.61: ICSP.2 U1.DIO6/TXD0
N$68
  Bottom 0.61: PWR.1 10.95,84.36 D1.1 D2.2
N$69
  Bottom 0.61: PWR.2 2.54,72.45 D3.1 D4.2
N$70
  Top 0.61: PGM.2 99.62,77.3 100.33,78.01 111.76,78.01 113.03,79.28 124.46,79.28 U1.SPIMISO
N$71
  Bottom 0.61: R29.2 6.35,52.61 7.62,51.34 Q4.2
N$72
  Bottom 0.61: R31.1 3.81,47.53 Q4.3
N$73
  Top 0.61: ICSP.1 U1.DIO4/CTS0
N$74
  Top 0.254: 105.41,67.85 U1.DIO5/RTS0 | 105.41,58.96 ICSP.5
  Top 0.61: 105.41,67.85 104.14,66.58 104.14,60.23 105.41,58.96
N$75
  Top 0.61: U1.DIO19/TXD1 124.46,43.72 123.83,43.09 Q3.2
N$76
  Top 0.254: U1.SPISSM 116.84,69.75 121.92,69.75 U1.SPISSZ
N$77
  Top 0.61: U1.DIO7/RXD0 109.22,65.31 107.95,64.04 ICSP.3
NEUTRE
  Top 1.5: 10.16,13.24 7.62,13.24 7.62,14.51 IN.1 | 10.16,13.24 20.32,13.24 | 20.32,13.24 25.4,13.24 | 25.4,13.24 35.56,13.24 | 35.56,13.24 40.64,13.24 | 40.64,13.24 50.8,13.24 | 50.8,13.24 55.88,13.24 | 55.88,13.24 66.04,13.24 | 66.04,13.24 71.12,13.24 | 71.12,13.24 81.28,13.24 | 81.28,13.24 86.36,13.24 | 86.36,13.24 96.52,13.24 | 96.52,13.24 101.6,13.24 | 101.6,13.24 111.76,13.24 | 111.76,13.24 116.84,13.24 | 116.84,13.24 127,13.24 T1.A1 121.92,18.32 R1C.2 | S8.1 10.16,6.97 10.16,13.24 | S7.1 25.4,6.97 25.4,13.24 | 20.32,13.24 T8.A1 15.24,18.32 R8C.2 | 35.56,13.24 T7.A1 30.48,18.32 R7C.2 | 50.8,13.24 T6.A1 45.72,18.32 R6C.2 | S6.1 40.64,6.97 40.64,13.24 | S5.1 55.88,6.97 55.88,13.24 | S4.1 71.12,6.97 71.12,13.24 | S3.1 86.36,6.97 86.36,13.24 | S2.1 101.6,6.97 101.6,13.24 | S1.1 116.84,6.97 116.84,13.24 | 66.04,13.24 T5.A1 60.96,18.32 R5C.2 | 81.28,13.24 T4.A1 76.2,18.32 R4C.2 | 96.52,13.24 T3.A1 91.44,18.32 R3C.2 | 111.76,13.24 T2.A1 106.68,18.32 R2C.2
PHASE
  Bottom 1.5: 27.94,15.78 27.94,14.51 34.29,8.16 S7.3 | 27.94,15.78 R7B.2 27.94,20.86 | S6.3 49.53,8.16 43.18,14.51 R6B.2 43.18,20.86 | S5.3 64.77,8.16 58.42,14.51 R5B.2 58.42,20.86 | S4.3 80.01,8.16 73.66,14.51 R4B.2 73.66,20.86 | S3.3 95.25,8.16 88.9,14.51 R3B.2 88.9,20.86 | S2.3 110.49,8.16 104.14,14.51 R2B.2 104.14,20.86 | S1.3 125.73,8.16 119.38,14.51 R1B.2 119.38,20.86 | 27.94,20.86 T8.A2 | 27.94,20.86 T7.A2 43.18,20.86 | 43.18,20.86 T6.A2 58.42,20.86 | 58.42,20.86 T5.A2 73.66,20.86 | 73.66,20.86 T4.A2 88.9,20.86 | 88.9,20.86 T3.A2 104.14,20.86 | 104.14,20.86 T2.A2 119.38,20.86 | 119.38,20.86 T1.A2 | 27.94,15.78 20.32,8.16 S8.3 19.05,8.16 12.7,14.51 R8B.2 12.7,19.42 IN.3
SYNC
  Top 0.61: R30.1 15.24,56.42 48.26,56.42 48.26,71.66 63.5,71.66 66.04,70.39 95.25,70.39 95.25,80.55 101.6,80.55 102.87,81.82 I4.3
  Bottom 0.61: I4.3 I3.3 | R31.2 R30.1
TERRE
  Bottom 1.5: 15.24,3.08 2.54,3.08 2.54,18.32 4.62,20.4 IN.2 | 15.24,3.08 30.48,3.08 | 30.48,3.08 45.72,3.08 | 45.72,3.08 60.96,3.08 | 60.96,3.08 76.2,3.08 | 76.2,3.08 91.44,3.08 | 91.44,3.08 106.68,3.08 | 106.68,3.08 121.33,3.08 S1.2 | S2.2 106.68,6.97 106.68,3.08 | S3.2 91.44,6.97 91.44,3.08 | S4.2 76.2,6.97 76.2,3.08 | S5.2 60.96,6.97 60.96,3.08 | S6.2 45.72,6.97 45.72,3.08 | S7.2 30.48,6.97 30.48,3.08 | S8.2 15.24,6.97 15.24,3.08
VCC
  Bottom 0.61: JP1.2 C4.2 REG_3.3V.IN 52.07,85.63 59.69,85.63 59.69,83.09 55.88,83.09 53.34,80.55 48.26,80.55 48.26,74.2 | EXT.9 45.72,50.07 46.99,48.8 52.07,48.8 53.34,50.07 53.34,74.2 | 48.26,74.2 29.21,74.2 IC3.20 24.13,72.93 22.86,71.66 19.05,71.66 17.78,70.39 17.78,62.77 R26.2 R30.2 | 48.26,74.2 53.34,74.2 | 53.34,74.2 58.42,74.2 IC1.20 R25.2 R28.1
VDD
  Top 0.61: U1.VDD 119.38,58.96 119.38,67.85 115.57,67.85 U1.SPISWP 115.57,74.2 102.87,74.2 101.6,72.93 101.6,58.96 R32.2
  Bottom 0.61: R32.2 92.71,58.96 90.17,61.5 88.9,61.5 80.01,70.39 74.93,70.39 74.93,74.2 73.66,75.47 67.31,75.47 67.31,80.55 66.04,81.82 C5.1 57.15,79.28 | REG_3.3V.OUT 57.15,79.28 | 57.15,79.28 +3.3V.1

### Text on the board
tPlace: Synchro | 12v~ | BARREAU Pascal | Jennic-Lumiere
